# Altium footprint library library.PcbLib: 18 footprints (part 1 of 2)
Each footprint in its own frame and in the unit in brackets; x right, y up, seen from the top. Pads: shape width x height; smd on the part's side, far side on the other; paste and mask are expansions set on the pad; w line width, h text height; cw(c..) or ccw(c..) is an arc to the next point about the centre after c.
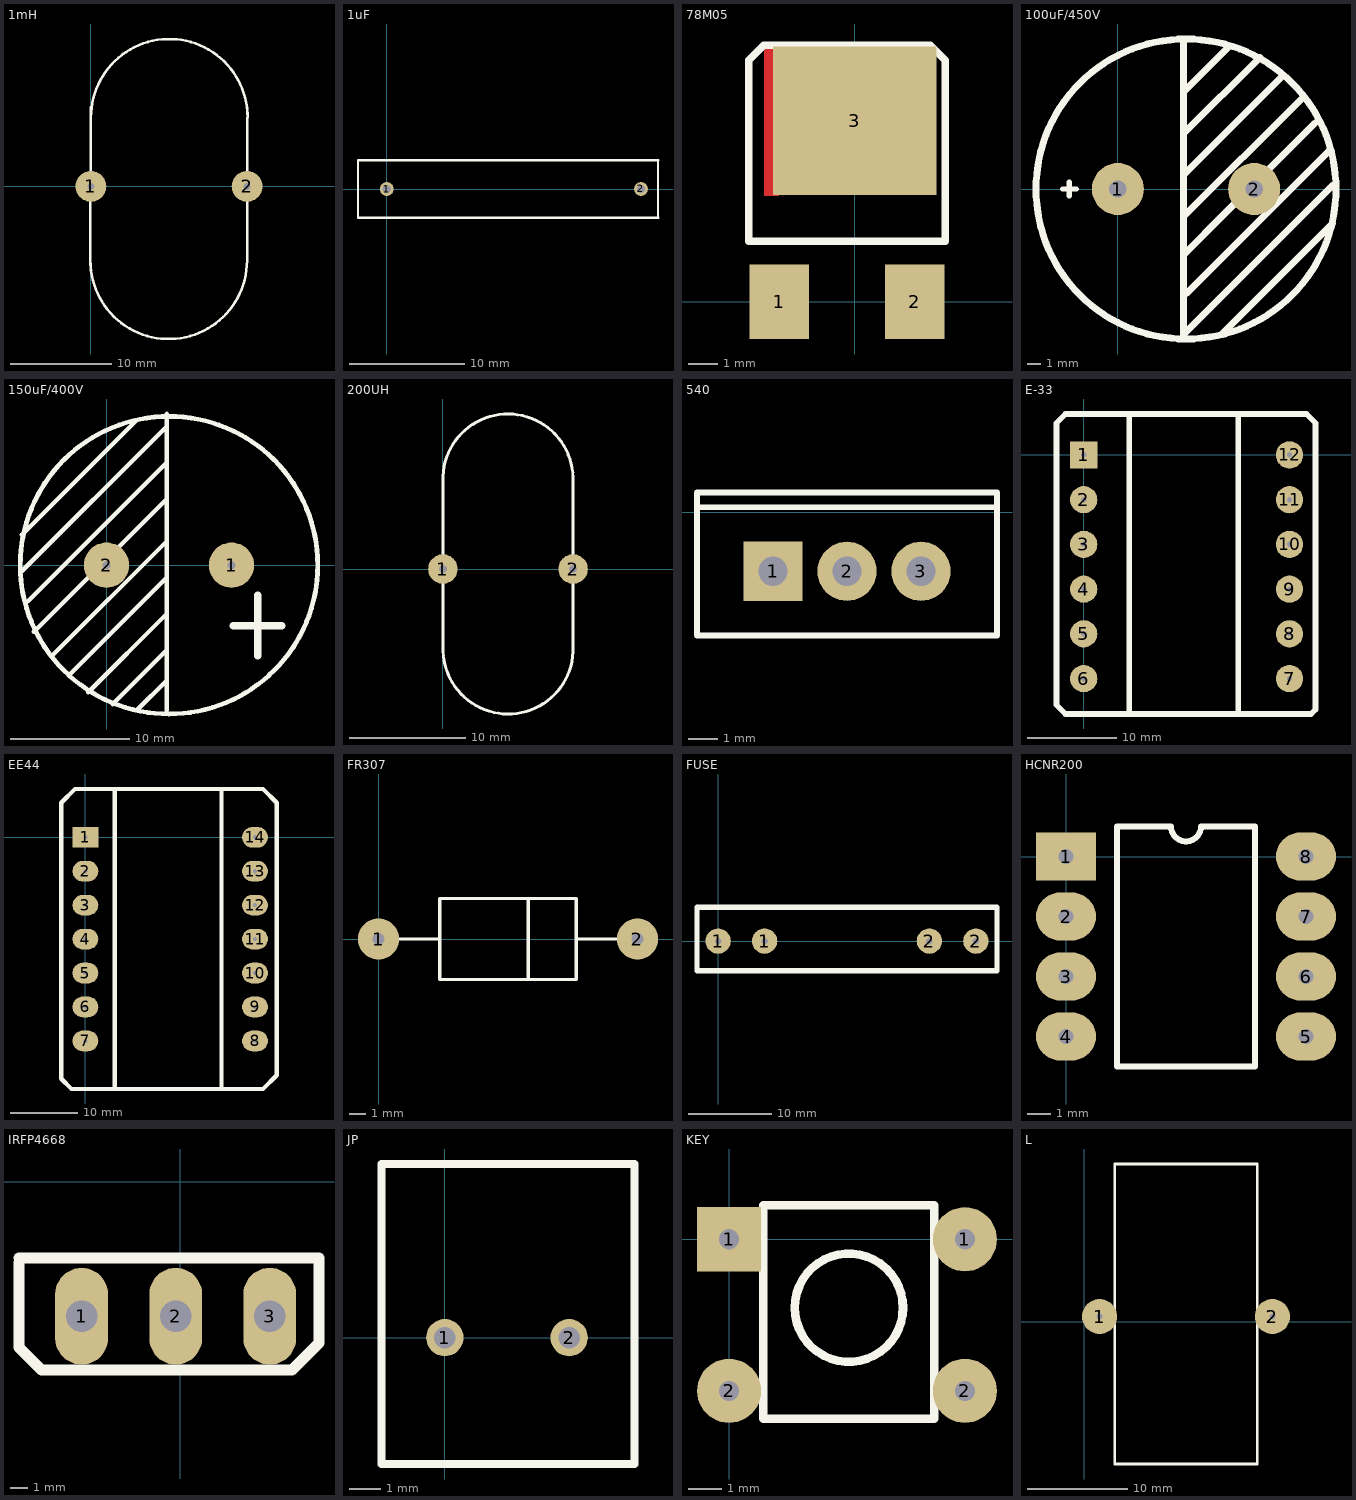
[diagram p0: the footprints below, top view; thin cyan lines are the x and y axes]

## 1mH [mil]
pads (2):
  round 120 hole 28: 1(0,0) 2(610,0)
Top Overlay:
  lines w10: -2.21,-2.21 -2.21,-290 ccw(c303.9,-290) 610,-290 610,0 610,267.79 ; 0,0 0,310 ; 0,270 cw(c306.1,270) 612.21,270

## 1uF [mm]
pads (2):
  round 1.2 hole 0.7: 1(0,0) 2(22.101,0)
Top Layer:
  lines w0.254: -0.003,0.254 0.003,-0.254
Top Overlay:
  lines w0.2: 15.1,-2.5 12.6,-2.5 0,-2.5 -2.5,-2.5 -2.5,2.5 0,2.5 12.6,2.5 15.1,2.5 ; 23.582,-2.5 23.582,2.5
  lines w0.254: 15.1,-2.5 23.582,-2.5 ; 15.1,2.5 23.582,2.5

## 78M05 [mm]
pads (3):
  rect 2x2.5 smd: 1(-2.54,0) 2(2.032,0)
  rect 5.5x5 smd: 3(0,6.096)
Top Layer:
  rectangle: -3.048,3.556 -2.54,8.636
Top Overlay:
  lines w0.254: -3.556,2.032 -3.556,2.286 -3.556,8.128 -3.048,8.636 2.032,8.636 2.54,8.636 3.048,8.128 3.048,2.032 -3.048,2.032 -3.556,2.032

## 100uF/450V [mm]
pads (2):
  round 3.81 hole 1.27: 1(0,0) 2(10,0)
Top Overlay:
  circle w0.508: c5.002,0 r11
  lines w0.381: -4.064,0 -3.048,0 ; -3.556,-0.508 -3.556,0.508
  lines w0.508: 4.826,-10.922 4.826,10.922 ; 4.826,-10.414 4.826,-10.668 15.748,0.254 ; 4.826,-7.62 5.08,-7.62 9.398,-3.302 9.906,-2.794 15.494,2.794 ; 4.826,-4.572 4.826,-4.826 7.874,-1.778 14.478,4.826 ; 4.826,-2.032 13.462,6.604 ; 4.826,1.27 4.826,1.016 11.938,8.128 ; 4.826,4.064 10.414,9.652 ; 4.826,7.112 8.128,10.414 ; 7.62,-10.668 7.874,-10.414 15.494,-2.794 15.748,-2.54

## 150uF/400V [mm]
pads (2):
  round 3.81 hole 0.7: 1(10.5,0) 2(0,0)
Top Overlay:
  circle w0.4: c5.25,0 r12.5
  lines w0.381: -7.112,-0.508 5.08,11.684 ; -7.112,2.54 2.54,12.192 ; -6.604,-3.048 5.08,8.636 ; -6.096,-5.588 5.08,5.588 ; -4.572,-7.62 5.08,2.032 ; -3.048,-9.144 5.08,-1.016 ; -1.524,-10.668 5.08,-4.064 ; 0.508,-11.684 5.08,-7.112 ; 2.54,-12.192 5.08,-9.652 ; 5.08,-12.192 5.08,12.7
  lines w0.635: 10.668,-5.08 14.732,-5.08 ; 12.7,-7.62 12.7,-2.54

## 200UH [mil]
pads (2):
  round 100 hole 28: 1(0,0) 2(440,0)
Top Overlay:
  lines w10: 0.15,-275.95 ccw(c220.15,-270.01) 440,-280 440,310 ccw(c220,304.06) 0.15,314.05 0.15,-275.95

## 540 [mil]
pads (3):
  rect 80x80 hole 39.37: 1(200,-80)
  round 80 hole 39.37: 2(300,-80) 3(400,-80)
Top Overlay:
  lines w7.87: 97.24,6.61 502.76,6.61 ; 97.24,-166.61 97.24,26.3 502.76,26.3 502.76,-166.61 97.24,-166.61

## E-33 [mm]
pads (12):
  rect 3.048x3.048 hole 0.6: 1(0,0)
  round 3.048 hole 0.6: 2(0,-5) 3(0,-10) 4(0,-15) 5(0,-20) 6(0,-25) 7(23,-25) 8(23,-20) 9(23,-15) 10(23,-10) 11(23,-5) 12(23,0)
Top Overlay:
  lines w0.2: -3.048,-27.432 -3.048,2.568 ; 1.998,-28.956 20.828,-28.956 ; 25.908,-27.432 25.908,2.568
  lines w0.635: -3.048,2.568 -3.048,3.556 -2.032,4.572 24.892,4.572 25.908,3.556 25.908,2.54 ; -3.048,3.048 -3.048,-27.94 -2.032,-28.956 20.32,-28.956 25.4,-28.956 25.908,-28.448 25.908,-26.924 25.908,2.568 ; 5.08,-28.956 5.08,4.572 ; 17.272,-28.956 17.272,4.572

## EE44 [mm]
pads (14):
  rect 3.81x3.048 hole 0.6: 1(0,0)
  oval 3.81x3.048 hole 0.6: 2(0,-5) 3(0,-10) 4(0,-15) 5(0,-20) 6(0,-25) 7(0,-30) 8(25,-30) 9(25,-25) 10(25,-20) 11(25,-15) 12(25,-10) 13(25,-5) 14(25,0)
Top Overlay:
  lines w0.635: 4.318,-37.084 4.318,7.112 ; 10.668,7.112 26.162,7.112 28.194,5.08 28.194,-35.052 26.162,-37.084 -2.032,-37.084 -3.556,-35.56 -3.556,5.08 -1.524,7.112 11.176,7.112 ; 20.066,-37.084 20.066,7.112

## FR307 [mil]
pads (2):
  round 100 hole 30: 1(0,0) 2(629.92,0)
Top Overlay:
  lines w7.87: 47.24,0 148.62,0 ; 364.5,-98.43 364.5,98.43 ; 481.3,0 582.68,0 ; 148.62,0 148.62,98.43 481.3,98.43 481.3,-98.43 148.62,-98.43 148.62,0

## FUSE [mil]
pads (4):
  round 120 hole 30: 1(0,0) 1(220,0) 2(1000,0) 2(1220,0)
Top Overlay:
  lines w25: -40,160 1320,160 1320,-140 -80,-140 -100,-140 -100,160 -30,160

## HCNR200 [mil]
pads (8):
  rect 100x80 hole 25: 1(0,0)
  oval 100x80 hole 25: 2(0,-100) 3(0,-200) 4(0,-300) 5(400,-300) 6(400,-200) 7(400,-100) 8(400,0)
Top Overlay:
  lines w10: 85,-350 85,50 175,50 ccw(c200,50) 225,50 315,50 315,-350 85,-350

## IRFP4668 [mm]
pads (3):
  oval 3x5.5 hole 1.8: 1(-5.588,-7.62) 2(-0.254,-7.62) 3(5.08,-7.62)
Top Overlay:
  lines w0.635: -9.144,-4.572 -9.144,-9.398 -7.874,-10.668 6.35,-10.668 7.874,-9.144 7.874,-4.318 -9.144,-4.318

## JP [mm]
pads (2):
  round 1.2 hole 0.7: 1(0,0) 2(4,0)
Top Overlay:
  lines w0.254: -2.032,-1.016 -2.032,0.508 ; -2.032,-0.254 -2.032,-4.064 6.096,-4.064 6.096,5.588 5.588,5.588 -2.032,5.588 -2.032,0

## KEY [mm]
pads (4):
  rect 1.905x1.905 hole 0.6: 1(0,0)
  round 1.905 hole 0.6: 1(7,0) 2(0,-4.5) 2(7,-4.5)
Top Overlay:
  circle w0.254: c3.556,-2.032 r1.606
  lines w0.254: 1.016,-5.334 1.016,1.016 6.096,1.016 6.096,0.762 6.096,-5.334 1.016,-5.334

## L [mm]
pads (2):
  round 3.5 hole 0.6: 1(1.524,0.508) 2(18.796,0.508)
Top Overlay:
  lines w0.254: 3.048,-14.224 3.048,15.748 17.272,15.748 17.272,-14.224 3.048,-14.224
